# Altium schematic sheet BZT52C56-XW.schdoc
size 127 x 101 mm
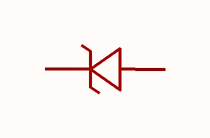
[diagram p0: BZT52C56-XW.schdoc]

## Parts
D?  bzt52c56_c523829  [SOD-123_L2.8-W1.8-LS3.7-RD]  (value not drawn)

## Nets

Not connected (* = marked no-connect by the designer): D? 1(K) 2(A)

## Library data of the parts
D? = bzt52c56_c523829: 二极管配置:1个独立式;稳压值(标称值):56V;稳压值(范围):53.2V~58.8V;耗散功率(Pd):500mW;; Manufacturer: MDD(辰达半导体); Symbol: BZT52C56-XW; AddInBom: yes; ModelId: 7884390a25fb4c08947731ebfba7e3f8; ModelTransform: 144.8816,62.992,0,0,0,0,0,0,0; Diode Configuration: 1个独立式; Zener Voltage(Nom): 56V; Reverse Leakage Current (Ir): 1uA@43V; Pd - Power Dissipation: 500mW; Impedance(Zzt): 180Ω; Tolerance: ±5%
